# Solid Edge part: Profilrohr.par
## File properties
Username: bmolnar
Dokumentum tartalom típus: 0
Author: bmolnar
Last saved by: bmolnar
Revision: 79
Sűrűség: 0,000 kg/m^3
Pontosság: 0,990
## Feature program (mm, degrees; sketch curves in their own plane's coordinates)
base feature "unnamed BaseFeature 1"
thread "Menet_1"  ThreadDepth = 9.3 mm
thread "unnamed Thread 1"
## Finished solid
Body 1: solid body, 199 faces, 486 edges, 308 vertices, 3 separate solids.
  Faces by surface: plane 108, cylinder 69, cone 18, torus 4
  Edges by curve: line 312, circle 164, curve on surface 7, spline 2, intersection 1
Bounding box of the edges (mm; curved faces can reach further): 124.000 x 131.000 x 76.000, from (-62, -62, 0) to (62, 69, 76).
Cylindrical faces by radius (mm): R0.2 x24, R2.625 x2, R5 x2, R5.5 x8, R5.7225 x4, R8.6 x14, R8.9 x2, R9 x2, R50 x1, R50.85 x2, R51.1 x2, R53.1 x2, R84 x4
Conical faces (half-angle, radius in mm at the cone's reference point): 30 deg R50.325 x2, 30 deg R51.283 x2, 45 deg R5.25 x4, 45 deg R6.0725 x2, 45 deg R8.65 x4, 45 deg R51.25 x4
Toroidal faces (ring radius, tube radius in mm): R52.9 r0.2 x4
Planar faces by outward normal: +x 9, +y 11, +z 12, -x 9, -y 9, -z 10, oblique 48
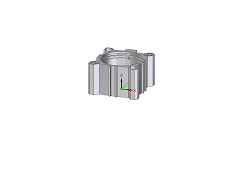
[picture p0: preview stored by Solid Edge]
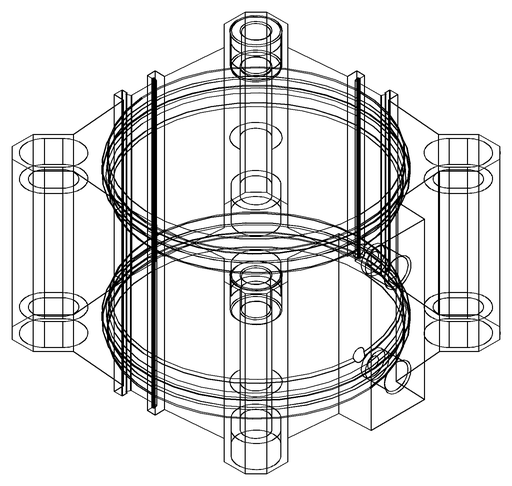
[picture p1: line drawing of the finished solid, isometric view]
